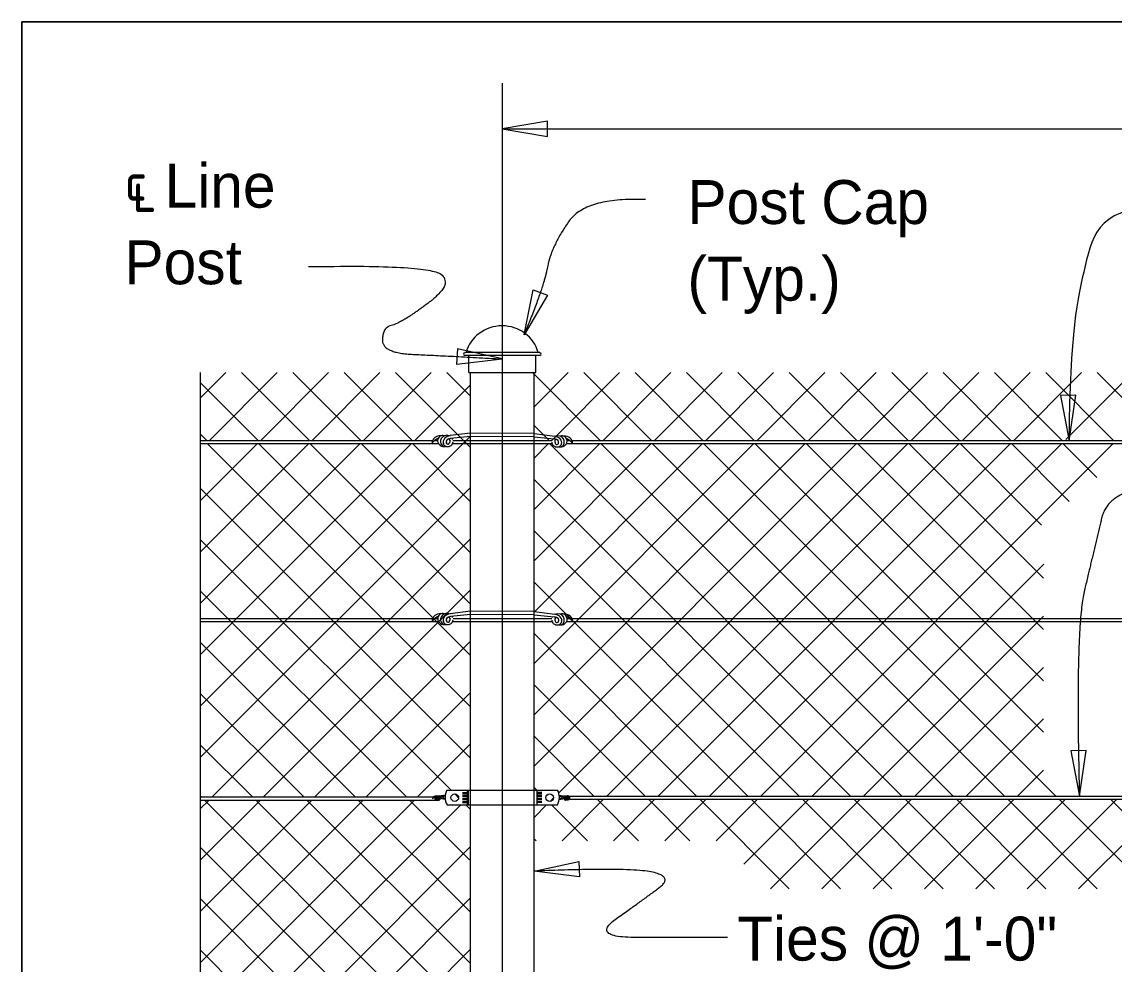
# Model space of a CAD drawing. Extents: x 0 to 41.2, y 0 to 26.
# Drawn here: x 0 to 5.02, y 21.63 to 25.96 of the extents above; entities that cross this region are included whole.
import ezdxf

# ---------------------------------------------------------------- set-up
doc = ezdxf.new("R2010")
doc.units = 0
for name, color, linetype in [('ActivePts-ConstElements', 7, 'Continuous'), ('CL_Major', 7, 'Continuous'), ('Dimension', 7, 'Continuous'), ('Miscellaneous', 7, 'Continuous'), ('Miscellaneous1', 7, 'Continuous'), ('SteelMisc', 7, 'Continuous'), ('SteelMisc_h', 7, 'Continuous'), ('TextStructures', 7, 'Continuous')]:
    doc.layers.add(name, color=color, linetype=linetype)

msp = doc.modelspace()

# ---------------------------------------------------------------- linework, layer by layer
at = {"layer": 'ActivePts-ConstElements'}
msp.add_lwpolyline([(0, 0), (41.2106, 0), (41.2106, 25.96), (0, 25.96)], close=True, dxfattribs=at)
at = {"layer": 'CL_Major'}
msp.add_line((2.2062, 25.6784), (2.2062, 14.8533), dxfattribs=at)
at = {"layer": 'Dimension'}
msp.add_line((2.2062, 25.4682), (22.2062, 25.4682), dxfattribs=at)
for points in [[(2.2062, 25.4682), (2.4145, 25.4329), (2.4145, 25.5035)], [(2.3061, 24.523), (2.3482, 24.73), (2.414, 24.7046)], [(2.2062, 24.4121), (2.0002, 24.4587), (1.9964, 24.3882)], [(4.8088, 24.0365), (4.8396, 24.2455), (4.769, 24.244)], [(4.8566, 22.4048), (4.8874, 22.6138), (4.8169, 22.6123)], [(2.3519, 22.0601), (2.5585, 22.1039), (2.5614, 22.0334)]]:
    msp.add_lwpolyline(points, close=True, dxfattribs=at)
msp.add_lwpolyline([(0.8194, 24.349), (0.8194, 21.1819), (0.9227, 21.1819), (0.8194, 21.1369), (0.716, 21.0919), (0.8194, 21.0919), (0.8194, 20.1983)], dxfattribs=at)
for points, degree in [([(2.8646, 25.1435), (2.5898, 25.1563), (2.4301, 24.926), (2.3965, 24.7387), (2.3061, 24.523)], 2), ([(5.2657, 25.0995), (4.9524, 25.1279), (4.8838, 24.8459), (4.8116, 24.5363), (4.8088, 24.0365)], 3), ([(1.3167, 24.8359), (1.8625, 24.8457), (1.9849, 24.7568), (1.7407, 24.5755), (1.6559, 24.5571), (1.6559, 24.4393), (1.9339, 24.427), (2.2062, 24.4121)], 2), ([(5.3115, 23.815), (4.9982, 23.8433), (4.9198, 23.5211), (4.8367, 23.1628), (4.8566, 22.4048)], 2), ([(3.2402, 21.7554), (3.0279, 21.7554), (2.6079, 21.7554), (2.8581, 21.9325), (2.9953, 22.0352), (2.7847, 22.0777), (2.352, 22.06)], 2)]:
    msp.add_open_spline(points, degree=degree, dxfattribs=at)
at = {"layer": 'Miscellaneous'}
for p, q in [((0.9371, 24.349), (0.8194, 24.2313)), ((1.1728, 24.349), (0.8602, 24.0365)), ((1.3218, 24.0365), (1.0093, 24.349)), ((1.4085, 24.349), (1.0959, 24.0365)), ((1.5575, 24.0365), (1.245, 24.349)), ((1.6442, 24.349), (1.3316, 24.0365)), ((1.7932, 24.0365), (1.4807, 24.349)), ((1.8799, 24.349), (1.5674, 24.0365)), ((2.0603, 24.0051), (1.7164, 24.349)), ((2.0603, 24.2408), (1.9521, 24.349)), ((2.658, 24.0365), (2.3455, 24.349)), ((2.509, 24.349), (2.352, 24.1921)), ((2.7447, 24.349), (2.4321, 24.0365)), ((2.8937, 24.0365), (2.5812, 24.349)), ((2.9804, 24.349), (2.6678, 24.0365)), ((3.1294, 24.0365), (2.8169, 24.349)), ((3.2161, 24.349), (2.9035, 24.0365)), ((3.3651, 24.0365), (3.0526, 24.349)), ((3.4518, 24.349), (3.1392, 24.0365)), ((3.6008, 24.0365), (3.2883, 24.349)), ((3.6875, 24.349), (3.3749, 24.0365)), ((3.8365, 24.0365), (3.524, 24.349)), ((3.9232, 24.349), (3.6106, 24.0365)), ((4.0722, 24.0365), (3.7597, 24.349)), ((4.1589, 24.349), (3.8463, 24.0365)), ((4.3079, 24.0365), (3.9954, 24.349)), ((4.3946, 24.349), (4.082, 24.0365)), ((4.5436, 24.0365), (4.2311, 24.349)), ((4.6303, 24.349), (4.3177, 24.0365)), ((4.7793, 24.0365), (4.4668, 24.349)), ((4.866, 24.349), (4.5535, 24.0365)), ((5.015, 24.0365), (4.7025, 24.349)), ((5.1017, 24.349), (4.7948, 24.0422)), ((5.2507, 24.0365), (4.9382, 24.349)), ((1.0861, 24.0365), (0.8194, 24.3033)), ((2.0603, 24.2938), (1.8031, 24.0365)), ((2.4223, 24.0365), (2.352, 24.1068)), ((2.0603, 24.0581), (0.8192, 22.817)), ((0.8504, 24.0365), (0.8194, 24.0676)), ((1.9047, 24.0365), (1.9002, 24.041)), ((1.7883, 24.0218), (0.8192, 23.0527)), ((1.5526, 24.0218), (0.8192, 23.2884)), ((1.3169, 24.0218), (0.8192, 23.5241)), ((1.0812, 24.0218), (0.8192, 23.7598)), ((2.0603, 22.8138), (0.8524, 24.0218)), ((2.0603, 23.0495), (1.0881, 24.0218)), ((2.0603, 23.2852), (1.3238, 24.0218)), ((2.0603, 23.5209), (1.5595, 24.0218)), ((2.0603, 23.7566), (1.7952, 24.0218)), ((3.8316, 24.0218), (2.352, 22.5421)), ((3.5959, 24.0218), (2.352, 22.7779)), ((3.3602, 24.0218), (2.352, 23.0136)), ((3.1245, 24.0218), (2.352, 23.2493)), ((2.8888, 24.0218), (2.352, 23.485)), ((2.6531, 24.0218), (2.352, 23.7207)), ((2.4174, 24.0218), (2.352, 23.9564)), ((4.0413, 22.4048), (2.4243, 24.0218)), ((4.0673, 24.0218), (2.4652, 22.4196)), ((4.277, 22.4048), (2.66, 24.0218)), ((4.303, 24.0218), (2.686, 22.4048)), ((4.5127, 22.4048), (2.8957, 24.0218)), ((4.5387, 24.0218), (2.9217, 22.4048)), ((4.7484, 22.4048), (3.1314, 24.0218)), ((4.7744, 24.0218), (3.1574, 22.4048)), ((4.6913, 22.6976), (3.3671, 24.0218)), ((5.0101, 24.0218), (3.3931, 22.4048)), ((4.6913, 22.9333), (3.6028, 24.0218)), ((4.6913, 23.169), (3.8385, 24.0218)), ((4.6913, 23.4047), (4.0742, 24.0218)), ((4.6827, 23.649), (4.3099, 24.0218)), ((4.8094, 23.758), (4.5456, 24.0218)), ((4.936, 23.8671), (4.7813, 24.0218)), ((3.8056, 22.4048), (2.352, 23.8583)), ((2.0603, 23.8224), (0.8192, 22.5813)), ((2.0603, 22.5781), (0.8194, 23.8191)), ((1.9708, 22.4319), (0.8194, 23.5834)), ((2.0603, 23.5867), (0.8745, 22.4009)), ((3.5699, 22.4048), (2.352, 23.6226)), ((4.6938, 23.4697), (3.6288, 22.4048)), ((3.3342, 22.4048), (2.352, 23.3869)), ((1.7662, 22.4009), (0.8194, 23.3477)), ((2.0603, 23.351), (1.1102, 22.4009)), ((4.6913, 23.2315), (3.8645, 22.4048)), ((1.9048, 23.219), (1.9004, 23.2235)), ((3.0985, 22.4048), (2.352, 23.1512)), ((1.5305, 22.4009), (0.8194, 23.112)), ((2.0603, 23.1153), (1.3459, 22.4009)), ((4.6913, 22.9958), (4.1002, 22.4048)), ((1.2948, 22.4009), (0.8194, 22.8763)), ((2.0603, 22.8796), (1.5816, 22.4009)), ((2.8628, 22.4048), (2.352, 22.9155)), ((4.6913, 22.7601), (4.3359, 22.4048)), ((2.6271, 22.4048), (2.352, 22.6798)), ((1.0591, 22.4009), (0.8194, 22.6406)), ((2.0603, 22.6439), (1.8173, 22.4009)), ((4.6913, 22.5244), (4.5716, 22.4048)), ((2.3642, 22.4319), (2.352, 22.4441)), ((0.8234, 22.4009), (0.8192, 22.405)), ((1.8028, 22.3863), (0.8192, 21.4028)), ((1.0955, 22.3862), (0.8192, 22.1099)), ((1.3313, 22.3862), (0.8192, 21.8742)), ((1.567, 22.3862), (0.8192, 21.6385)), ((0.8598, 22.3861), (0.8192, 22.3456)), ((2.0603, 21.1639), (0.8381, 22.3861)), ((2.0603, 21.3996), (1.0738, 22.3862)), ((2.0603, 21.6353), (1.3094, 22.3862)), ((2.0603, 21.871), (1.5451, 22.3862)), ((2.0559, 22.1112), (1.7808, 22.3863)), ((2.0058, 22.3969), (1.9883, 22.4144)), ((2.4419, 22.3963), (2.426, 22.3805)), ((2.6712, 22.39), (2.4806, 22.1994)), ((2.8325, 22.1994), (2.6418, 22.39)), ((2.9069, 22.39), (2.7163, 22.1994)), ((3.0682, 22.1994), (2.8775, 22.39)), ((3.1427, 22.39), (2.952, 22.1994)), ((3.5244, 21.9789), (3.1132, 22.39)), ((3.3784, 22.39), (3.1877, 22.1994)), ((3.6141, 22.39), (3.3156, 22.0916)), ((3.7601, 21.9789), (3.3489, 22.39)), ((3.8498, 22.39), (3.4386, 21.9789)), ((3.9958, 21.9789), (3.5846, 22.39)), ((4.0855, 22.39), (3.6743, 21.9789)), ((4.2315, 21.9789), (3.8203, 22.39)), ((4.3212, 22.39), (3.91, 21.9789)), ((4.4672, 21.9789), (4.056, 22.39)), ((4.5569, 22.39), (4.1457, 21.9789)), ((4.7029, 21.9789), (4.2917, 22.39)), ((4.7926, 22.39), (4.3814, 21.9789)), ((4.9386, 21.9789), (4.5274, 22.39)), ((5.0283, 22.39), (4.6171, 21.9789)), ((5.1743, 21.9789), (4.7631, 22.39)), ((5.264, 22.39), (4.8528, 21.9789)), ((7.2458, 20.143), (4.9988, 22.39)), ((2.0163, 22.3642), (0.8341, 21.1819)), ((2.0603, 22.3424), (2.0386, 22.3642)), ((2.4097, 22.3642), (2.352, 22.3064)), ((2.5968, 22.1994), (2.432, 22.3642)), ((2.0603, 22.1725), (0.8192, 20.9314)), ((2.3611, 22.1994), (2.352, 22.2084)), ((2.0603, 20.9282), (0.8192, 22.1693)), ((2.0603, 21.9368), (0.8192, 20.6957)), ((2.0603, 20.6925), (0.8192, 21.9336)), ((2.0603, 21.701), (0.8192, 20.46)), ((2.0603, 20.4568), (0.8192, 21.6979))]:
    msp.add_line(p, q, dxfattribs=at)
at = {"layer": 'Miscellaneous1'}
msp.add_lwpolyline([(0, 25.96), (41.2106, 25.96), (41.2106, 0), (0, 0)], close=True, dxfattribs=at)
at = {"layer": 'SteelMisc'}
for p, q in [((2.3786, 24.441), (2.0339, 24.441)), ((2.0339, 24.4288), (2.3786, 24.4288)), ((2.0521, 24.349), (2.0521, 24.4288)), ((2.3603, 24.349), (2.3603, 24.4288)), ((2.0521, 24.349), (2.3603, 24.349)), ((2.0603, 17.8646), (2.0603, 24.349)), ((2.352, 17.8646), (2.352, 24.349)), ((1.8858, 24.0365), (0.8192, 24.0365)), ((1.9095, 24.0365), (1.8943, 24.0365)), ((2.0608, 24.0708), (1.9665, 24.0597)), ((2.0608, 24.0563), (1.9686, 24.0469)), ((2.0603, 24.0365), (1.9799, 24.0365)), ((2.3519, 24.0691), (2.0608, 24.0708)), ((2.3519, 24.0546), (2.0608, 24.0563)), ((2.3519, 24.0691), (2.4468, 24.058)), ((2.3519, 24.0546), (2.4445, 24.0451)), ((2.4341, 24.0365), (2.3519, 24.0365)), ((2.5172, 24.0365), (2.504, 24.0365)), ((11.9229, 24.0365), (2.5271, 24.0365)), ((1.9144, 24.0218), (0.8192, 24.0218)), ((2.0603, 24.0218), (1.9772, 24.0218)), ((2.4355, 24.0218), (2.3519, 24.0218)), ((11.9243, 24.0218), (2.5005, 24.0218)), ((2.0609, 23.2533), (1.9666, 23.2422)), ((2.0609, 23.2388), (1.9688, 23.2294)), ((2.3521, 23.2516), (2.0609, 23.2533)), ((2.3521, 23.2371), (2.0609, 23.2388)), ((2.3521, 23.2516), (2.447, 23.2405)), ((2.3521, 23.2371), (2.4447, 23.2276)), ((1.886, 23.219), (0.8194, 23.219)), ((1.9146, 23.2043), (0.8194, 23.2043)), ((1.9097, 23.219), (1.8945, 23.219)), ((2.0604, 23.2043), (1.9774, 23.2043)), ((2.0604, 23.219), (1.98, 23.219)), ((2.4343, 23.219), (2.3521, 23.219)), ((2.4357, 23.2043), (2.3521, 23.2043)), ((11.9244, 23.2043), (2.5006, 23.2043)), ((2.5173, 23.219), (2.5042, 23.219)), ((11.9231, 23.219), (2.5273, 23.219)), ((1.9522, 22.4319), (2.4601, 22.4319)), ((2.0466, 22.3642), (2.0466, 22.4319)), ((2.0504, 22.3642), (2.0504, 22.4319)), ((2.3657, 22.3642), (2.3657, 22.4319)), ((0.8194, 22.4009), (1.8897, 22.4009)), ((0.8194, 22.3861), (1.916, 22.3863)), ((1.9443, 22.389), (1.9104, 22.3947)), ((1.9439, 22.3938), (1.9137, 22.3987)), ((1.9449, 22.4094), (1.9182, 22.405)), ((1.9442, 22.4044), (1.9182, 22.4002)), ((1.9352, 22.403), (1.9352, 22.3951)), ((2.0236, 22.4211), (2.0466, 22.4211)), ((2.0236, 22.4155), (2.0466, 22.4155)), ((2.0236, 22.4075), (2.0466, 22.4075)), ((2.0236, 22.402), (2.0466, 22.402)), ((2.0236, 22.394), (2.0466, 22.394)), ((2.0236, 22.3884), (2.0466, 22.3884)), ((2.0236, 22.3804), (2.0466, 22.3804)), ((2.0236, 22.3749), (2.0466, 22.3749)), ((2.3886, 22.4211), (2.3657, 22.4211)), ((2.3886, 22.4155), (2.3657, 22.4155)), ((2.3886, 22.4075), (2.3657, 22.4075)), ((2.3886, 22.402), (2.3657, 22.402)), ((2.3886, 22.394), (2.3657, 22.394)), ((2.3886, 22.3884), (2.3657, 22.3884)), ((2.3886, 22.3804), (2.3657, 22.3804)), ((2.3886, 22.3749), (2.3657, 22.3749)), ((2.4674, 22.4094), (2.4967, 22.4048)), ((2.468, 22.389), (2.5017, 22.3946)), ((2.4681, 22.4044), (2.4942, 22.4003)), ((2.4684, 22.3937), (2.4983, 22.3987)), ((2.477, 22.4029), (2.477, 22.3951)), ((2.5108, 22.4048), (11.8852, 22.4048)), ((2.5141, 22.39), (11.9118, 22.39)), ((1.9524, 22.3642), (2.4597, 22.3642))]:
    msp.add_line(p, q, dxfattribs=at)
for centre, start, end in [((2.034, 24.4347), 91.1647, 268.8353), ((2.3783, 24.4347), 271.1647, 88.8353)]:
    msp.add_arc(centre, 0.00613, start, end, dxfattribs=at)
for centre, major_axis, ratio, start_param, end_param in [((2.2054, 24.4), (-0.1711, 0), 0.957868, 3.394611, 6.030583), ((1.9208, 24.024), (0.0373, 0), 0.957868, 1.486836, 3.108042), ((1.9419, 23.9843), (-0.0724, 0), 0.957868, 5.162149, 5.652106), ((1.9344, 24.036), (-0.0249, 0), 0.957868, 6.009018, 7.089857), ((1.9333, 24.0385), (0.023, 0), 0.957868, 1.29026, 2.970541), ((1.952, 24.0331), (0.0295, 0), 0.957868, 1.220941, 4.039556), ((1.9655, 24.0349), (-0.0303, -0.0108), 0.724765, 4.35367, 6.324556), ((1.9622, 24.0308), (-0.0139, 0), 0.957868, 5.22362, 6.905413), ((1.9565, 24.0284), (-0.00795, 0), 0.957868, 6.140374, 9.314262), ((1.9706, 24.022), (-0.0259, 0), 0.957868, 4.777514, 5.62749), ((1.9548, 24.0342), (0.0119, 0), 0.957868, 5.725876, 7.416677), ((1.9548, 24.0342), (0.0119, 0), 0.957868, 5.639684, 5.723117), ((1.9551, 24.033), (0.0251, 0), 0.957868, 5.531357, 6.227833), ((1.9551, 24.033), (0.0251, 0), 0.957868, 0.407687, 0.609214), ((2.4586, 24.0312), (-0.0251, 0), 0.957868, 0.055352, 0.751829), ((2.4586, 24.0312), (-0.0251, 0), 0.957868, 5.673972, 5.875498), ((2.4481, 24.0331), (0.0303, -0.0108), 0.724765, 6.241815, 8.212701), ((2.4431, 24.0202), (0.0259, 0), 0.957868, 0.655696, 1.505671), ((2.4588, 24.0325), (-0.0119, 0), 0.957868, 5.149694, 6.840495), ((2.4571, 24.0267), (0.00795, 0), 0.957868, 3.252108, 6.425997), ((2.4616, 24.0313), (-0.0295, 0), 0.957868, 2.243629, 5.062245), ((2.4514, 24.029), (0.0139, 0), 0.957868, 5.660958, 7.342751), ((2.4803, 24.0367), (-0.023, 0), 0.957868, 3.312645, 4.992926), ((2.4928, 24.0222), (-0.0373, 0), 0.957868, 3.175144, 4.79635), ((2.4792, 24.0342), (0.0249, 0), 0.957868, 5.476514, 6.557353), ((2.4717, 23.9825), (0.0724, 0), 0.957868, 0.631079, 1.121037), ((1.9358, 24.032), (0.0231, 0), 0.957868, 3.779554, 4.879821), ((1.9419, 24.0263), (0.0206, -0.0021), 0.798607, 4.32653, 5.220153), ((1.9554, 24.0263), (0.0206, -0.0021), 0.798607, 3.333154, 5.220153), ((1.948, 24.045), (0.0391, 0), 0.957868, 5.082588, 5.41974), ((2.4656, 24.0433), (-0.0391, 0), 0.957868, 0.863445, 1.200597), ((2.4588, 24.0325), (-0.0119, 0), 0.957868, 0.560069, 0.643501), ((2.4582, 24.0245), (-0.0206, -0.0021), 0.798607, 1.063032, 2.950031), ((2.4717, 24.0245), (-0.0206, -0.0021), 0.798607, 1.063032, 1.956656), ((2.4778, 24.0302), (-0.0231, 0), 0.957868, 1.403365, 2.503632), ((1.921, 23.2065), (0.0373, 0), 0.957868, 1.486836, 3.108042), ((1.9421, 23.1668), (-0.0724, 0), 0.957868, 5.162149, 5.652106), ((1.9346, 23.2185), (-0.0249, 0), 0.957868, 6.009018, 7.089857), ((1.9335, 23.221), (0.023, 0), 0.957868, 1.29026, 2.970541), ((1.9522, 23.2156), (0.0295, 0), 0.957868, 1.220941, 4.039556), ((1.9657, 23.2174), (-0.0303, -0.0108), 0.724765, 4.35367, 6.324556), ((1.9624, 23.2134), (-0.0139, 0), 0.957868, 5.22362, 6.905413), ((1.9707, 23.2045), (-0.0259, 0), 0.957868, 4.777514, 5.62749), ((1.955, 23.2168), (0.0119, 0), 0.957868, 5.725876, 7.416677), ((1.9552, 23.2155), (0.0251, 0), 0.957868, 0.407687, 0.609214), ((2.4588, 23.2138), (-0.0251, 0), 0.957868, 5.673972, 5.875498), ((2.4433, 23.2027), (0.0259, 0), 0.957868, 0.655696, 1.505671), ((2.4483, 23.2157), (0.0303, -0.0108), 0.724765, 6.241815, 8.212701), ((2.459, 23.215), (-0.0119, 0), 0.957868, 5.149694, 6.840495), ((2.4618, 23.2139), (-0.0295, 0), 0.957868, 2.243629, 5.062245), ((2.4805, 23.2192), (-0.023, 0), 0.957868, 3.312645, 4.992926), ((2.493, 23.2048), (-0.0373, 0), 0.957868, 3.175144, 4.79635), ((2.4719, 23.1651), (0.0724, 0), 0.957868, 0.631079, 1.121037), ((1.936, 23.2145), (0.0231, 0), 0.957868, 3.779554, 4.879821), ((1.9421, 23.2088), (0.0206, -0.0021), 0.798607, 4.32653, 5.220153), ((1.9556, 23.2088), (0.0206, -0.0021), 0.798607, 3.333154, 5.220153), ((1.9567, 23.211), (-0.00795, 0), 0.957868, 6.140374, 9.314262), ((1.9482, 23.2276), (0.0391, 0), 0.957868, 5.082588, 5.41974), ((1.955, 23.2168), (0.0119, 0), 0.957868, 5.639684, 5.723117), ((1.9552, 23.2155), (0.0251, 0), 0.957868, 5.531357, 6.227833), ((2.4588, 23.2138), (-0.0251, 0), 0.957868, 0.055352, 0.751829), ((2.4658, 23.2258), (-0.0391, 0), 0.957868, 0.863445, 1.200597), ((2.459, 23.215), (-0.0119, 0), 0.957868, 0.560069, 0.643501), ((2.4573, 23.2092), (0.00795, 0), 0.957868, 3.252108, 6.425997), ((2.4584, 23.207), (-0.0206, -0.0021), 0.798607, 1.063032, 2.950031), ((2.4516, 23.2116), (0.0139, 0), 0.957868, 5.660958, 7.342751), ((2.4719, 23.207), (-0.0206, -0.0021), 0.798607, 1.063032, 1.956656), ((2.478, 23.2127), (-0.0231, 0), 0.957868, 1.403365, 2.503632), ((2.4794, 23.2167), (0.0249, 0), 0.957868, 5.476514, 6.557353), ((2.0214, 22.3983), (-0.0776, 0), 0.957868, 5.81433, 6.762456), ((2.3908, 22.3983), (0.0776, 0), 0.957868, 5.803915, 6.752041), ((1.9, 22.3915), (0.0142, 0), 0.957868, 1.427866, 3.10804), ((1.908, 22.3765), (-0.0274, 0), 0.957868, 5.133531, 5.652105), ((1.9052, 22.3961), (-0.00944, 0), 0.957868, 5.913863, 8.247076), ((1.9047, 22.397), (0.00872, 0), 0.957868, 1.103089, 2.861068), ((1.9047, 22.397), (0.00503, 0), 0.92697, 1.632124, 4.493683), ((1.9113, 22.3965), (0.00872, 0), 0.957868, 1.202886, 4.168248), ((1.9169, 22.3957), (-0.0115, -0.0041), 0.737732, 4.35367, 7.518104), ((1.9157, 22.3941), (-0.00527, 0), 0.957868, 5.822913, 6.90541), ((1.9135, 22.3932), (-0.00301, 0), 0.957868, 5.79353, 6.278592), ((1.9189, 22.3908), (-0.00982, 0), 0.957868, 4.777514, 5.64637), ((1.9135, 22.3932), (-0.00301, 0), 0.957868, 0.785393, 3.285656), ((1.9129, 22.3954), (0.00453, 0), 0.957868, 0.731188, 1.133458), ((1.913, 22.3949), (0.0095, 0), 0.957868, 5.036011, 6.030719), ((1.913, 22.3949), (0.0095, 0), 0.957868, 0.267283, 0.659981), ((2.4993, 22.3949), (-0.0095, 0), 0.957868, 5.673972, 6.052579), ((2.4993, 22.3949), (-0.0095, 0), 0.957868, 0.252467, 1.271421), ((2.4934, 22.3908), (0.00982, 0), 0.957868, 0.655696, 1.505671), ((2.4953, 22.3957), (0.0115, -0.0041), 0.737732, 5.08821, 8.212701), ((2.4987, 22.3932), (0.00301, 0), 0.957868, 3.28349, 5.170635), ((2.4993, 22.3954), (-0.00453, 0), 0.957868, 5.149727, 5.551998), ((2.4966, 22.3941), (0.00527, 0), 0.957868, 5.058829, 7.342751), ((2.501, 22.3965), (-0.00872, 0), 0.957868, 2.1008, 4.992926), ((2.4987, 22.3932), (0.00301, 0), 0.957868, 0.004594, 0.141897), ((2.5071, 22.3961), (0.00944, 0), 0.957868, 4.316497, 6.557353), ((2.5075, 22.397), (-0.00872, 0), 0.957868, 3.323334, 4.992926), ((2.5075, 22.397), (-0.00503, 0), 0.92697, 1.780895, 4.712389)]:
    msp.add_ellipse(centre, major_axis=major_axis, ratio=ratio, start_param=start_param, end_param=end_param, dxfattribs=at)
for centre, major_axis in [((1.9881, 22.3974), (0.0178, 0)), ((2.4241, 22.3974), (-0.0178, 0))]:
    msp.add_ellipse(centre, major_axis=major_axis, ratio=0.957868, dxfattribs=at)
at = {"layer": 'SteelMisc_h'}
for p, q in [((2.3519, 24.0365), (2.0603, 24.0365)), ((2.3519, 24.0218), (2.0603, 24.0218)), ((2.3521, 23.219), (2.0604, 23.219)), ((2.3521, 23.2043), (2.0604, 23.2043))]:
    msp.add_line(p, q, dxfattribs=at)

# ---------------------------------------------------------------- texts
at = {"layer": 'Dimension'}
for s, p in [('℄ Line ', (0.4713, 25.1069)), ('Post Cap ', (3.0566, 25.0317)), ('Post', (0.4713, 24.7549)), ('(Typ.)', (3.0566, 24.6797))]:
    msp.add_text(s, height=0.2016, dxfattribs=at).set_placement(p)
at = {"layer": 'TextStructures'}
msp.add_text('Ties @ 1\'-0" ', height=0.2016, dxfattribs=at).set_placement((3.285, 21.6493))

doc.saveas('drawing.dxf')
